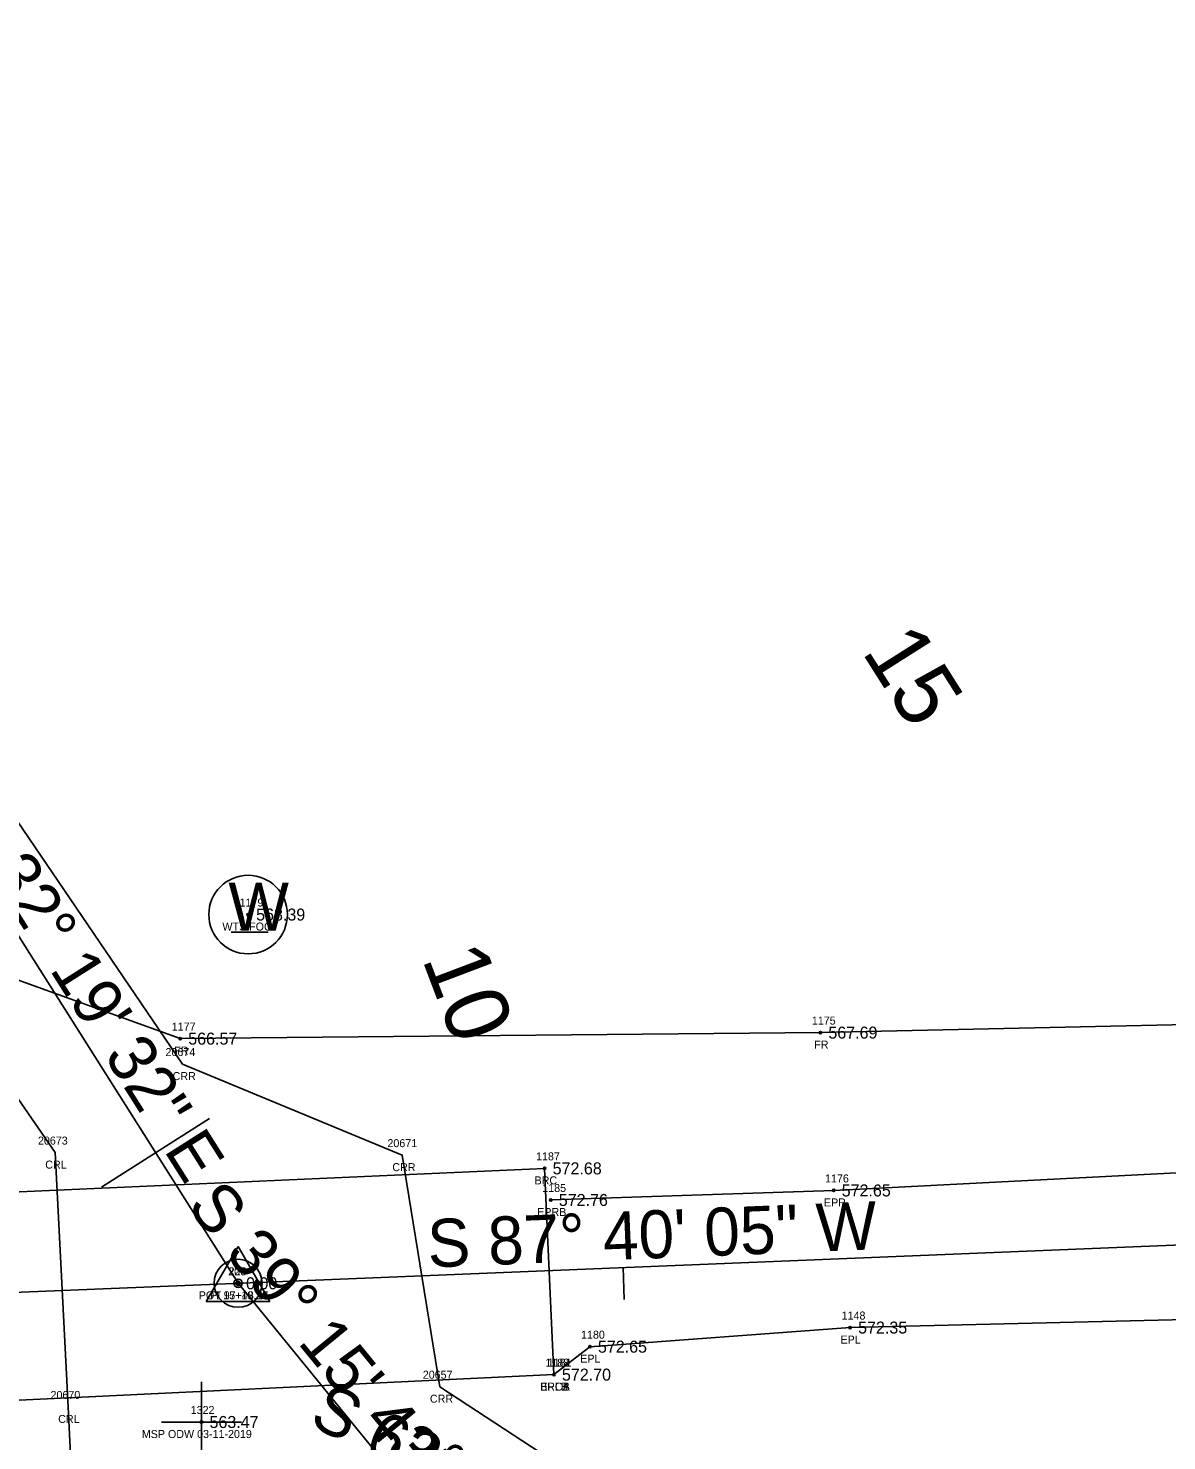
# Model space of a CAD drawing. Extents: x 1529475 to 1532053, y 876698 to 877911.
# Drawn here: x 1530875.7 to 1531018, y 877254.2 to 877430.7 of the extents above; entities that cross this region are included whole.
import ezdxf

# ---------------------------------------------------------------- set-up
doc = ezdxf.new("R2010")
doc.units = 0
for name, color, linetype in [('RD_EX_Bridge', 7, 'Continuous'), ('RD_EX_Bridge_txCode', 7, 'Continuous'), ('RD_EX_Fence_Other', 7, 'Continuous'), ('RD_EX_Fence_Other_txCode', 7, 'Continuous'), ('RD_EX_H2O', 7, 'Continuous'), ('RD_EX_H2O_txCode', 7, 'Continuous'), ('RD_EX_Road', 7, 'Continuous'), ('RD_EX_Road_txCode', 7, 'Continuous'), ('RD_EX_TX_Bridge_ELEV', 7, 'Continuous'), ('RD_EX_TX_Fence_Other_ELEV', 7, 'Continuous'), ('RD_EX_TX_Misc_ELEV', 7, 'Continuous'), ('RD_EX_TX_Road_ELEV', 7, 'Continuous'), ('RD_EX_TX_UT_ELEV', 7, 'Continuous'), ('RD_EX_UT', 7, 'Continuous'), ('RD_EX_UT_txCode', 7, 'Continuous'), ('RD_HC_Cl', 7, 'Continuous'), ('RD_HC_Data', 7, 'Continuous'), ('RD_HC_Data_Tic', 7, 'Continuous'), ('RD_HC_Survey_ELEV', 7, 'Continuous'), ('RD_HC_TX_Sta50', 7, 'Continuous'), ('RD_HC_txCode', 7, 'Continuous'), ('RD_SMD_Locator', 7, 'Continuous')]:
    doc.layers.add(name, color=color, linetype=linetype)

msp = doc.modelspace()

# ---------------------------------------------------------------- linework, layer by layer
at = {"layer": 'RD_EX_Bridge'}
msp.add_lwpolyline([(1530941.45, 877262.44), (1530866.77, 877258.87), (1530865.25, 877284.85), (1530940.29, 877288.21), (1530941.45, 877262.44)], dxfattribs=at)
at = {"layer": 'RD_EX_Fence_Other'}
msp.add_lwpolyline([(1531024.55, 877377.19), (1531037.25, 877334.84), (1531041.63, 877306.64), (1530974.75, 877305.17), (1530894.74, 877304.42), (1530859.11, 877317.26)], dxfattribs=at)
at = {"layer": 'RD_EX_H2O'}
for p, q in [((1530897.4, 877251.52), (1530897.4, 877261.52)), ((1530892.4, 877256.52), (1530902.4, 877256.52))]:
    msp.add_line(p, q, dxfattribs=at)
for points in [[(1531030.35, 877191.82), (1530971.87, 877223.83), (1530957.12, 877241.36), (1530927.2, 877260.93), (1530922.5, 877289.86), (1530895.04, 877301.24), (1530872.88, 877333.85), (1530860.22, 877363.17), (1530828.43, 877393.28), (1530808.3, 877433.62), (1530784.24, 877462.07), (1530773.36, 877492.12), (1530746.47, 877535.88), (1530723.52, 877580.98), (1530706.2, 877619.34), (1530689.1, 877649.27), (1530633.62, 877702.51)], [(1530972.1, 877196.48), (1530925.87, 877229.17), (1530918.34, 877241.35), (1530897.53, 877235.99), (1530881.25, 877248.19), (1530880.72, 877258.4), (1530879.1, 877290.18), (1530865.94, 877309.23), (1530832.49, 877347.64), (1530816.44, 877373.18)]]:
    msp.add_lwpolyline(points, dxfattribs=at)
msp.add_circle((1530897.4, 877256.52), 0.15, dxfattribs=at)
at = {"layer": 'RD_EX_Road'}
for points in [[(1531606.64, 877133.84), (1531579.15, 877155.05), (1531564.87, 877165.27), (1531535.22, 877186.03), (1531511.53, 877200.27), (1531474.57, 877218.9), (1531430.45, 877239.35), (1531404.48, 877249.38), (1531382.32, 877256.43), (1531333.23, 877270.71), (1531303.67, 877277.44), (1531276.52, 877282.71), (1531237.32, 877287.2), (1531185.8, 877290.94), (1531132.61, 877292.77), (1531081.11, 877292.38), (1531038.69, 877288.67), (1530976.42, 877285.45), (1530941.06, 877284.26)], [(1531595.27, 877120.27), (1531553.56, 877149.9), (1531509.97, 877177.57), (1531465.94, 877201.73), (1531423.65, 877222), (1531376.09, 877237.68), (1531328.84, 877252.31), (1531282.81, 877261.85), (1531235.7, 877268.49), (1531185.47, 877272.84), (1531132.72, 877273.12), (1531080.2, 877271.87), (1531029.21, 877269.53), (1530978.47, 877268.32), (1530945.95, 877265.93), (1530941.45, 877262.44)]]:
    msp.add_lwpolyline(points, dxfattribs=at)
at = {"layer": 'RD_EX_UT'}
msp.add_line((1530901.1, 877317.71), (1530905.73, 877317.71), dxfattribs=at)
msp.add_circle((1530903.23, 877319.92), 4.91, dxfattribs=at)
at = {"layer": 'RD_HC_Cl'}
for p, q in [((1530858.7, 877342.25), (1530901.97, 877273.85)), ((1531122.76, 877282.84), (1530785.95, 877269.13)), ((1530901.97, 877273.85), (1530921.83, 877249.56))]:
    msp.add_line(p, q, dxfattribs=at)
at = {"layer": 'RD_HC_Data'}
for p, q in [((1530898, 877271.56), (1530901.98, 877278.44)), ((1530901.98, 877278.44), (1530905.94, 877271.56)), ((1530898, 877271.56), (1530905.94, 877271.56))]:
    msp.add_line(p, q, dxfattribs=at)
for radius in [3, 0.529, 0.282]:
    msp.add_circle((1530901.97, 877273.85), radius, dxfattribs=at)
at = {"layer": 'RD_HC_Data_Tic'}
for p, q in [((1530891.66, 877290.15), (1530898.42, 877294.43)), ((1530891.66, 877290.15), (1530884.9, 877285.87)), ((1530950.09, 877275.81), (1530950.25, 877271.81))]:
    msp.add_line(p, q, dxfattribs=at)
at = {"layer": 'RD_SMD_Locator'}
for centre in [(1530903.23, 877319.92), (1530974.75, 877305.17), (1530894.74, 877304.42), (1530940.29, 877288.21), (1530976.42, 877285.45), (1530941.06, 877284.26), (1530901.97, 877273.85), (1530901.97, 877273.85), (1530978.47, 877268.32), (1530945.95, 877265.93), (1530941.45, 877262.44), (1530941.45, 877262.44), (1530941.45, 877262.44)]:
    msp.add_circle(centre, 0.15, dxfattribs=at)

# ---------------------------------------------------------------- texts
at = {"layer": 'RD_EX_Bridge_txCode'}
for s, p in [('1187', (1530939.22, 877289.21)), ('BRC', (1530939.03, 877286.21)), ('1182', (1530940.38, 877263.44)), ('1188', (1530940.38, 877263.44)), ('BRCA', (1530939.71, 877260.44)), ('BRCB', (1530939.72, 877260.44))]:
    msp.add_text(s, height=1, dxfattribs=at).set_placement(p)
at = {"layer": 'RD_EX_Fence_Other_txCode'}
for s, p in [('1175', (1530973.69, 877306.17)), ('1177', (1530893.68, 877305.42)), ('FR', (1530893.99, 877302.42)), ('FR', (1530973.99, 877303.17))]:
    msp.add_text(s, height=1, dxfattribs=at).set_placement(p)
at = {"layer": 'RD_EX_H2O_txCode'}
for s, p in [('20674', (1530892.9, 877302.24)), ('CRR', (1530893.79, 877299.24)), ('20673', (1530876.96, 877291.18)), ('20671', (1530920.64, 877290.86)), ('CRL', (1530877.87, 877288.18)), ('CRR', (1530921.25, 877287.86)), ('20657', (1530925.06, 877261.93)), ('20670', (1530878.53, 877259.4)), ('CRR', (1530925.95, 877258.93)), ('CRL', (1530879.49, 877256.4)), ('1322', (1530896.05, 877257.52)), ('MSP ODW 03-11-2019', (1530889.94, 877254.52))]:
    msp.add_text(s, height=1, dxfattribs=at).set_placement(p)
at = {"layer": 'RD_EX_Road_txCode'}
for s, p in [('1176', (1530975.34, 877286.45)), ('1185', (1530939.99, 877285.26)), ('EPR', (1530975.2, 877283.45)), ('EPRB', (1530939.36, 877282.26)), ('1148', (1530977.41, 877269.32)), ('1180', (1530944.84, 877266.93)), ('EPL', (1530977.27, 877266.32)), ('1181', (1530940.67, 877263.44)), ('EPL', (1530944.74, 877263.93)), ('EPLB', (1530939.77, 877260.44))]:
    msp.add_text(s, height=1, dxfattribs=at).set_placement(p)
at = {"layer": 'RD_EX_TX_Bridge_ELEV'}
for s, p in [('572.68', (1530941.29, 877287.46)), ('572.70', (1530942.45, 877261.69)), ('572.70', (1530942.45, 877261.69))]:
    msp.add_text(s, height=1.5, dxfattribs=at).set_placement(p)
at = {"layer": 'RD_EX_TX_Fence_Other_ELEV'}
for s, p in [('566.57', (1530895.74, 877303.67)), ('567.69', (1530975.75, 877304.42))]:
    msp.add_text(s, height=1.5, dxfattribs=at).set_placement(p)
at = {"layer": 'RD_EX_TX_Misc_ELEV'}
msp.add_text('563.47', height=1.5, dxfattribs=at).set_placement((1530898.4, 877255.77))
at = {"layer": 'RD_EX_TX_Road_ELEV'}
for s, p in [('572.65', (1530977.42, 877284.7)), ('572.76', (1530942.06, 877283.51)), ('572.35', (1530979.47, 877267.57)), ('572.65', (1530946.95, 877265.18)), ('572.70', (1530942.45, 877261.69))]:
    msp.add_text(s, height=1.5, dxfattribs=at).set_placement(p)
at = {"layer": 'RD_EX_TX_UT_ELEV'}
msp.add_text('568.39', height=1.5, dxfattribs=at).set_placement((1530904.23, 877319.17))
at = {"layer": 'RD_EX_UT'}
msp.add_text('W', height=6, dxfattribs=at).set_placement((1530900.76, 877317.92))
at = {"layer": 'RD_EX_UT_txCode'}
for s, p in [('1179', (1530902.16, 877320.92)), ('WTS FOC', (1530900.01, 877317.92))]:
    msp.add_text(s, height=1, dxfattribs=at).set_placement(p)
at = {"layer": 'RD_HC_Data'}
for s, rotation, p in [('S 32%%d 19\' 32" E', 302.3255, (1530866.61, 877331.6)), ('S 39%%d 15\' 43" E', 309.262, (1530895.44, 877283.43)), ('S 87%%d 40\' 05" W', 2.3321, (1530925.75, 877275.82)), ('S 63%%d 28\' 51" E', 333.4808, (1530910.68, 877256.24))]:
    msp.add_text(s, height=6, rotation=rotation, dxfattribs=at).set_placement(p)
at = {"layer": 'RD_HC_Survey_ELEV'}
msp.add_text('0.00', height=1.5, dxfattribs=at).set_placement((1530902.97, 877273.1))
msp.add_text('0.00', height=1.5, dxfattribs=at).set_placement((1530902.97, 877273.1))
at = {"layer": 'RD_HC_TX_Sta50'}
for s, rotation, p in [('15', 302.3255, (1530979.85, 877352.77)), ('10', 290.7269, (1530924.93, 877314.4))]:
    msp.add_text(s, height=8, rotation=rotation, dxfattribs=at).set_placement(p)
at = {"layer": 'RD_HC_txCode'}
for s, p in [('206', (1530900.73, 877274.85)), ('223', (1530900.79, 877274.85)), ('POT 97+48.15', (1530897.06, 877271.85)), ('PI 15+19.28', (1530898.48, 877271.85))]:
    msp.add_text(s, height=1, dxfattribs=at).set_placement(p)

doc.saveas('drawing.dxf')
